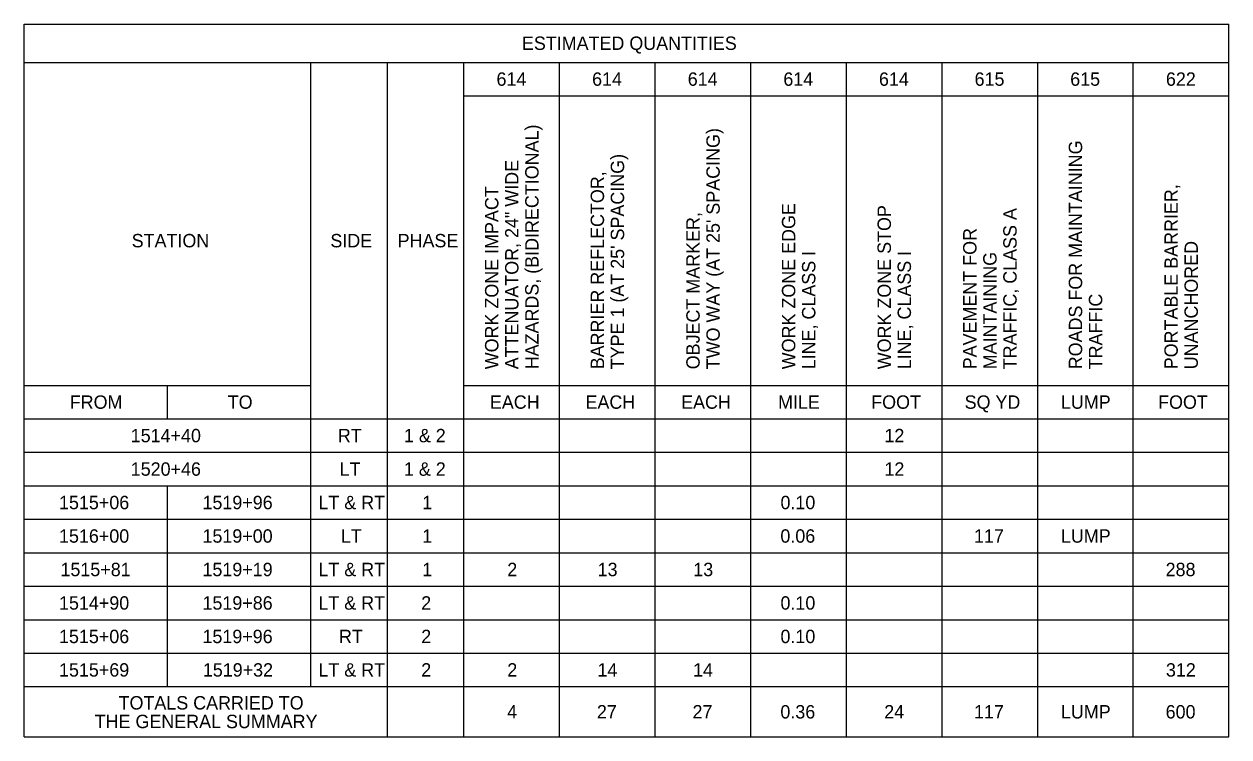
# Model space of a CAD drawing. Extents: x -37 to 104, y -26 to 49.
# Drawn here: x 91.66 to 104.26, y -2.66 to 4.79 of the extents above; entities that cross this region are included whole.
import ezdxf

# ---------------------------------------------------------------- set-up
doc = ezdxf.new("R2010")
doc.units = 0
doc.layers.add('SH_Text', color=7, linetype='Continuous')

msp = doc.modelspace()

# ---------------------------------------------------------------- linework, layer by layer
at = {"layer": 'SH_Text'}
for p, q in [((91.663, -2.663), (91.663, 4.789)), ((91.663, 4.789), (104.263, 4.789)), ((104.263, -2.663), (104.263, 4.789)), ((91.663, 4.389), (104.263, 4.389)), ((94.663, -2.138), (94.663, 4.389)), ((95.463, -2.663), (95.463, 4.389)), ((96.263, -2.663), (96.263, 4.389)), ((97.263, -2.663), (97.263, 4.389)), ((98.263, -2.663), (98.263, 4.389)), ((99.263, -2.663), (99.263, 4.389)), ((100.263, -2.663), (100.263, 4.389)), ((101.263, -2.663), (101.263, 4.389)), ((102.263, -2.663), (102.263, 4.389)), ((103.263, -2.663), (103.263, 4.389)), ((96.263, 4.039), (104.263, 4.039)), ((91.663, 1.012), (94.663, 1.012)), ((93.163, 0.662), (93.163, 1.012)), ((96.263, 1.012), (104.263, 1.012)), ((91.663, 0.662), (104.263, 0.662)), ((91.663, 0.312), (104.263, 0.312)), ((91.663, -0.038), (104.263, -0.038)), ((93.163, -2.138), (93.163, -0.038)), ((91.663, -0.388), (104.263, -0.388)), ((91.663, -0.738), (104.263, -0.738)), ((91.663, -1.088), (104.263, -1.088)), ((91.663, -1.438), (104.263, -1.438)), ((91.663, -1.788), (104.263, -1.788)), ((91.663, -2.138), (104.263, -2.138)), ((91.663, -2.663), (104.263, -2.663))]:
    msp.add_line(p, q, dxfattribs=at)

# ---------------------------------------------------------------- texts
for s, p in [('ESTIMATED QUANTITIES', (96.869, 4.519)), ('614', (96.603, 4.144)), ('614', (97.603, 4.144)), ('614', (98.603, 4.144)), ('614', (99.603, 4.144)), ('614', (100.603, 4.144)), ('615', (101.603, 4.144)), ('615', (102.603, 4.144)), ('622', (103.604, 4.144)), ('STATION', (92.788, 2.455)), ('SIDE', (94.866, 2.455)), ('PHASE', (95.569, 2.455)), ('FROM', (92.14, 0.767)), ('TO', (93.792, 0.767)), ('EACH', (96.534, 0.767)), ('EACH', (97.534, 0.767)), ('EACH', (98.534, 0.767)), ('MILE', (99.548, 0.767)), ('FOOT', (100.522, 0.767)), ('SQ YD', (101.499, 0.767)), ('LUMP', (102.506, 0.767)), ('FOOT', (103.522, 0.767)), ('1514+40', (92.778, 0.417)), ('RT', (94.944, 0.417)), ('1 & 2', (95.635, 0.417)), ('12', (100.66, 0.417)), ('1520+46', (92.778, 0.067)), ('LT', (94.963, 0.067)), ('1 & 2', (95.635, 0.067)), ('12', (100.66, 0.067)), ('1515+06', (92.028, -0.283)), ('1519+96', (93.528, -0.283)), ('LT & RT', (94.741, -0.283)), ('1', (95.827, -0.283)), ('0.10', (99.573, -0.283)), ('1516+00', (92.028, -0.633)), ('1519+00', (93.528, -0.633)), ('LT', (94.975, -0.633)), ('1', (95.827, -0.633)), ('0.06', (99.572, -0.633)), ('117', (101.597, -0.633)), ('LUMP', (102.506, -0.633)), ('1515+81', (92.043, -0.983)), ('1519+19', (93.528, -0.983)), ('LT & RT', (94.741, -0.983)), ('1', (95.827, -0.983)), ('2', (96.716, -0.983)), ('13', (97.661, -0.983)), ('13', (98.661, -0.983)), ('288', (103.601, -0.983)), ('1514+90', (92.028, -1.333)), ('1519+86', (93.528, -1.333)), ('LT & RT', (94.741, -1.333)), ('2', (95.816, -1.333)), ('0.10', (99.573, -1.333)), ('1515+06', (92.028, -1.683)), ('1519+96', (93.528, -1.683)), ('RT', (94.956, -1.683)), ('2', (95.816, -1.683)), ('0.10', (99.573, -1.683)), ('1515+69', (92.028, -2.033)), ('1519+32', (93.532, -2.033)), ('LT & RT', (94.741, -2.033)), ('2', (95.816, -2.033)), ('2', (96.716, -2.033)), ('14', (97.659, -2.033)), ('14', (98.659, -2.033)), ('312', (103.604, -2.033)), ('TOTALS CARRIED TO', (92.651, -2.377)), ('4', (96.714, -2.471)), ('27', (97.653, -2.471)), ('27', (98.653, -2.471)), ('0.36', (99.572, -2.471)), ('24', (100.658, -2.471)), ('117', (101.597, -2.471)), ('LUMP', (102.506, -2.471)), ('600', (103.601, -2.471)), ('THE GENERAL SUMMARY', (92.401, -2.572))]:
    msp.add_text(s, height=0.14, dxfattribs=at).set_placement(p)
for s, p in [('HAZARDS, (BIDIRECTIONAL)', (97.043, 1.18)), ("TWO WAY (AT 25' SPACING)", (98.938, 1.18)), ('ROADS FOR MAINTAINING', (102.728, 1.18)), ("TYPE 1 (AT 25' SPACING)", (97.938, 1.18)), ('ATTENUATOR, 24" WIDE', (96.833, 1.18)), ('BARRIER REFLECTOR,', (97.728, 1.18)), ('WORK ZONE IMPACT', (96.623, 1.18)), ('PORTABLE BARRIER,', (103.728, 1.18)), ('WORK ZONE EDGE', (99.728, 1.18)), ('OBJECT MARKER,', (98.728, 1.18)), ('WORK ZONE STOP', (100.728, 1.18)), ('TRAFFIC, CLASS A', (102.043, 1.18)), ('PAVEMENT FOR', (101.623, 1.18)), ('LINE, CLASS I', (99.938, 1.18)), ('LINE, CLASS I', (100.938, 1.18)), ('UNANCHORED', (103.938, 1.18)), ('MAINTAINING', (101.833, 1.18)), ('TRAFFIC', (102.938, 1.18))]:
    msp.add_text(s, height=0.14, rotation=90, dxfattribs=at).set_placement(p)

doc.saveas('drawing.dxf')
